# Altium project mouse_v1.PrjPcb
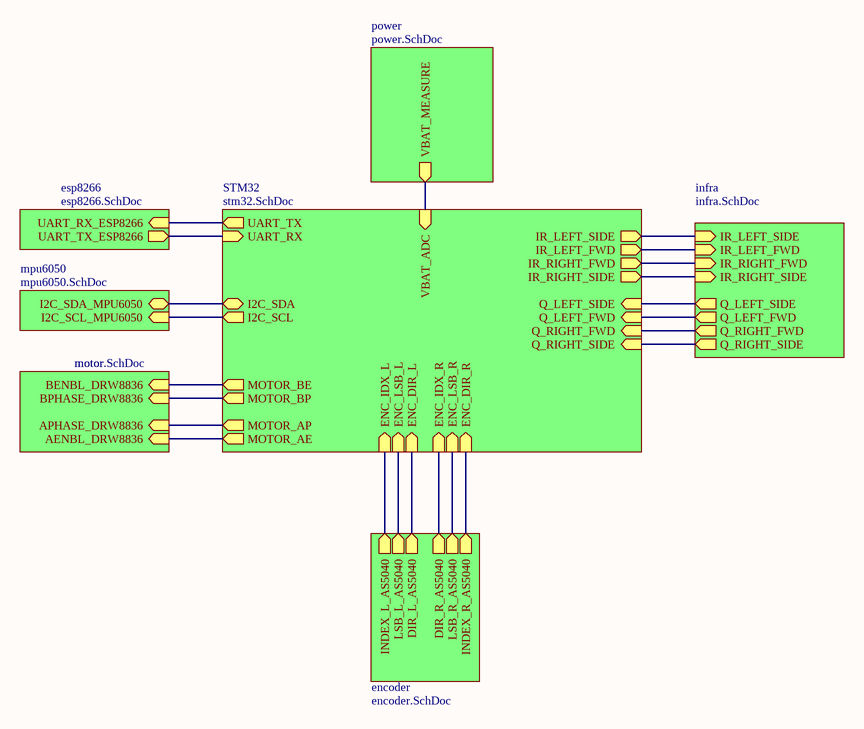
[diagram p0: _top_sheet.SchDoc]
8 sheets, 95 parts. Net scope: hierarchical (ports join the sheet entries above them; power ports are global).
Board file: grabovsky.PcbDoc
Sheets:
  _top_sheet.SchDoc
    STM32 = stm32.SchDoc
    infra = infra.SchDoc
    mpu6050 = mpu6050.SchDoc
    motor = motor.SchDoc
    power = power.SchDoc
    encoder = encoder.SchDoc
    esp8266 = esp8266.SchDoc

## Sheet _top_sheet.SchDoc
size A4

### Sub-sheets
encoder = encoder.SchDoc: INDEX_L_AS5040 (out), INDEX_R_AS5040 (out), LSB_L_AS5040 (out), DIR_L_AS5040 (out), DIR_R_AS5040 (out), LSB_R_AS5040 (out)
esp8266 = esp8266.SchDoc: UART_TX_ESP8266 (out), UART_RX_ESP8266 (in)
infra = infra.SchDoc: IR_LEFT_SIDE (in), IR_LEFT_FWD (in), IR_RIGHT_SIDE (in), IR_RIGHT_FWD (in), Q_LEFT_FWD (out), Q_LEFT_SIDE (out), Q_RIGHT_FWD (out), Q_RIGHT_SIDE (out)
motor = motor.SchDoc: AENBL_DRW8836 (in), APHASE_DRW8836 (in), BENBL_DRW8836 (in), BPHASE_DRW8836 (in)
mpu6050 = mpu6050.SchDoc: I2C_SCL_MPU6050 (in), I2C_SDA_MPU6050 (bidir)
power = power.SchDoc: VBAT_MEASURE (out)
STM32 = stm32.SchDoc: UART_TX (out), I2C_SDA (bidir), UART_RX (in), I2C_SCL (out), MOTOR_AE (out), MOTOR_BE (out), MOTOR_BP (out), MOTOR_AP (out), Q_RIGHT_FWD (in), Q_RIGHT_SIDE (in), Q_LEFT_FWD (in), Q_LEFT_SIDE (in), IR_LEFT_SIDE (out), IR_LEFT_FWD (out), IR_RIGHT_FWD (out), IR_RIGHT_SIDE (out), ENC_IDX_L (in), ENC_LSB_L (in), ENC_DIR_L (in), ENC_IDX_R (in), ENC_LSB_R (in), ENC_DIR_R (in), VBAT_ADC (in)

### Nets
VBAT: sheet STM32/VBAT_ADC, sheet power/VBAT_MEASURE
Net*1_3: sheet STM32/ENC_LSB_L, sheet encoder/LSB_L_AS5040
Net*1_4: sheet STM32/ENC_DIR_L, sheet encoder/DIR_L_AS5040
Net*1_6: sheet STM32/ENC_IDX_L, sheet encoder/INDEX_L_AS5040
Net*2_3: sheet STM32/ENC_LSB_R, sheet encoder/LSB_R_AS5040
Net*2_4: sheet STM32/ENC_IDX_R, sheet encoder/DIR_R_AS5040
Net*2_6: sheet STM32/ENC_DIR_R, sheet encoder/INDEX_R_AS5040
Netmosfet1_2: sheet STM32/IR_LEFT_FWD, sheet infra/IR_LEFT_FWD
Netmosfet1_5: sheet STM32/IR_LEFT_SIDE, sheet infra/IR_LEFT_SIDE
Netmosfet2_2: sheet STM32/IR_RIGHT_SIDE, sheet infra/IR_RIGHT_SIDE
Netmosfet2_5: sheet STM32/IR_RIGHT_FWD, sheet infra/IR_RIGHT_FWD
NetP3_2: sheet STM32/UART_TX, sheet esp8266/UART_RX_ESP8266
NetP3_3: sheet STM32/UART_RX, sheet esp8266/UART_TX_ESP8266
NetR9_3: sheet STM32/Q_LEFT_FWD, sheet infra/Q_LEFT_FWD
NetR10_3: sheet STM32/Q_LEFT_SIDE, sheet infra/Q_LEFT_SIDE
NetR11_3: sheet STM32/Q_RIGHT_SIDE, sheet infra/Q_RIGHT_SIDE
NetR12_3: sheet STM32/Q_RIGHT_FWD, sheet infra/Q_RIGHT_FWD
NetR16_1: sheet STM32/I2C_SDA, sheet mpu6050/I2C_SDA_MPU6050
NetR19_1: sheet STM32/I2C_SCL, sheet mpu6050/I2C_SCL_MPU6050
NetR28_1: sheet STM32/MOTOR_AP, sheet motor/APHASE_DRW8836
NetR29_1: sheet STM32/MOTOR_BP, sheet motor/BPHASE_DRW8836
NetR30_1: sheet STM32/MOTOR_BE, sheet motor/BENBL_DRW8836
NetR31_1: sheet STM32/MOTOR_AE, sheet motor/AENBL_DRW8836

## Sheet stm32.SchDoc
size A4
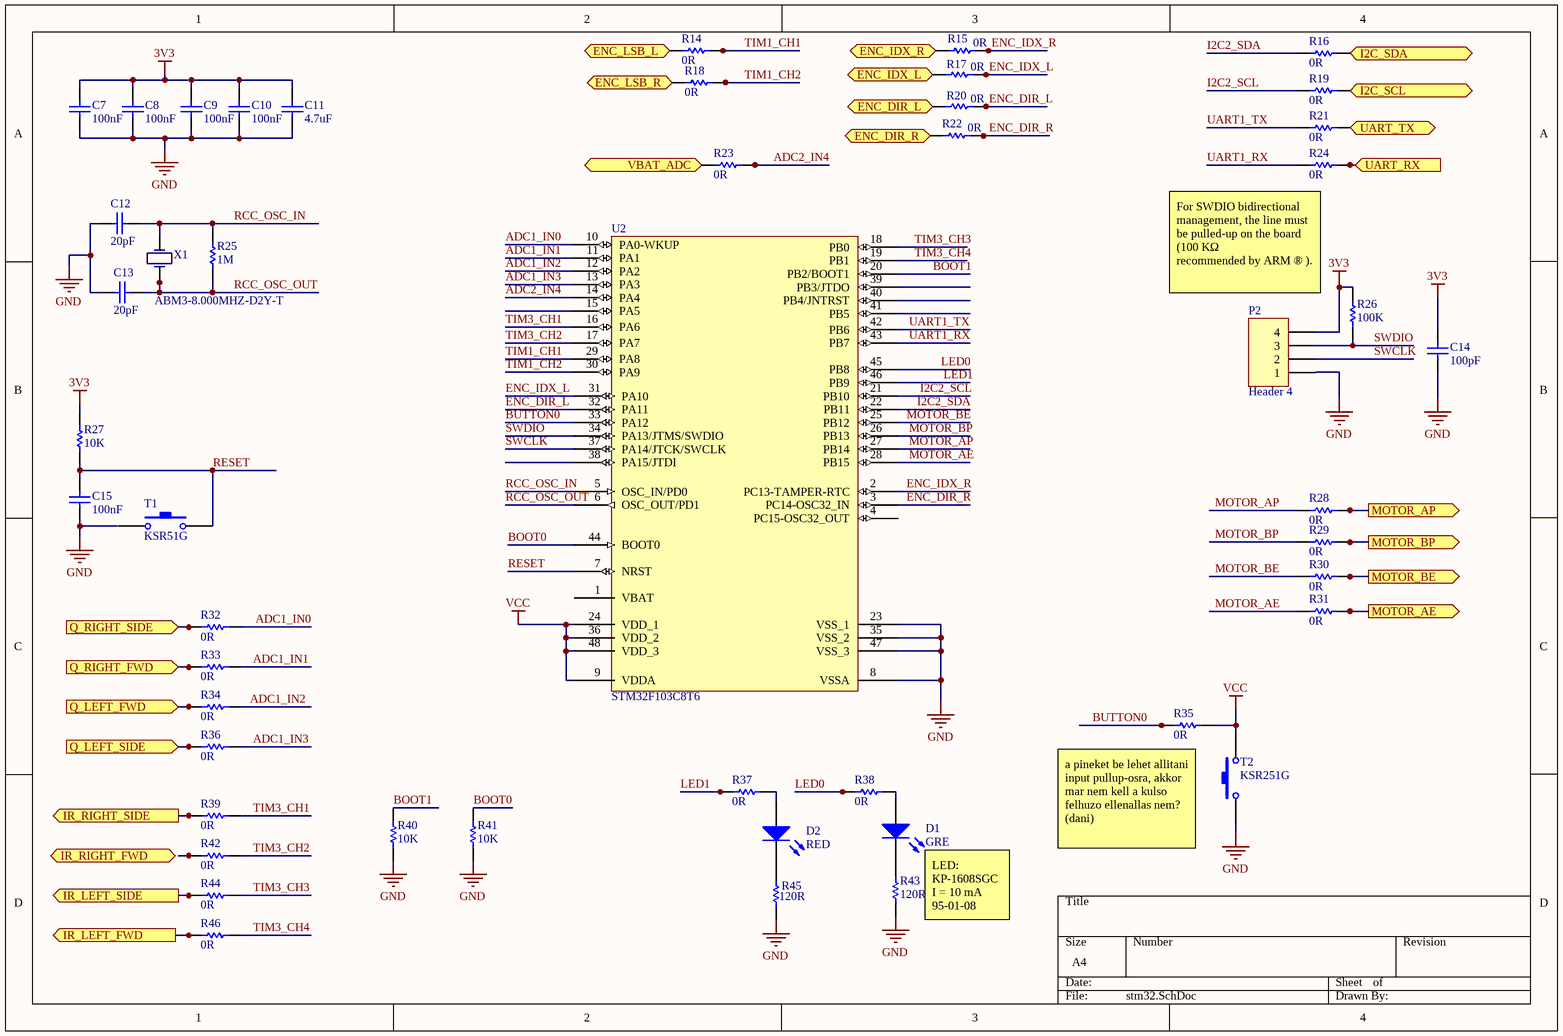
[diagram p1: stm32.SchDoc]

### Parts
C7  100nF  [0603]
C8  100nF  [0603]
C9  100nF  [0603]
C10  100nF  [0603]
C11  4.7uF  [0603]
C12  20pF  [0603]
C13  20pF  [0603]
C14  100pF  [0603]
C15  100nF  [0603]
D1  GRE  [1608[0603]]
D2  RED  [1608[0603]]
P2  Header 4  [HDR1X4]
R14  0R  [0402]
R15  0R  [0402]
R16  0R  [0402]
R17  0R  [0402]
R18  0R  [0402]
R19  0R  [0402]
R20  0R  [0402]
R21  0R  [0402]
R22  0R  [0402]
R23  0R  [0402]
R24  0R  [0402]
R25  1M  [0603]
R26  100K  [0603]
R27  10K  [0603]
R28  0R  [0402]
R29  0R  [0402]
R30  0R  [0402]
R31  0R  [0402]
R32  0R  [0402]
R33  0R  [0402]
R34  0R  [0402]
R35  0R  [0402]
R36  0R  [0402]
R37  0R  [0402]
R38  0R  [0402]
R39  0R  [0402]
R40  10K  [0603]
R41  10K  [0603]
R42  0R  [0402]
R43  120R  [0603]
R44  0R  [0402]
R45  120R  [0603]
R46  0R  [0402]
T1  KSR51G  [ksr251g]
T2  KSR251G  [ksr251g]
U2  STM32F103C8T6  [LQFP48_N]
X1  ABM3-8.000MHZ-D2Y-T  [Crystal]

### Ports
ENC_DIR_L (in), ENC_DIR_R (in), ENC_IDX_L (in), ENC_IDX_R (in), ENC_LSB_L (in), ENC_LSB_R (in), I2C_SCL (out), I2C_SDA (bidir), IR_LEFT_FWD (out), IR_LEFT_SIDE (out), IR_RIGHT_FWD (out), IR_RIGHT_SIDE (out), MOTOR_AE (out), MOTOR_AP (out), MOTOR_BE (out), MOTOR_BP (out), Q_LEFT_FWD (in), Q_LEFT_SIDE (in), Q_RIGHT_FWD (in), Q_RIGHT_SIDE (in), UART_RX (in), UART_TX (out), VBAT_ADC (in)

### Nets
3V3: C7.5 C8.5 C9.5 C10.5 C11.5 C14.5 P2.4 R26.4 R27.3
GND: C7.6 C8.6 C9.6 C10.6 C11.6 C12.5 C13.5 C14.6 C15.5 P2.1 R40.4 R41.4 R43.4 R45.4 T2.1 U2.8(VSSA) U2.23(VSS_1) U2.35(VSS_2) U2.47(VSS_3)
VBAT: R23.0 ; port VBAT_ADC
VCC: R35.1 T2.2 U2.9(VDDA) U2.24(VDD_1) U2.36(VDD_2) U2.48(VDD_3)
ADC1_IN0: R32.1 U2.10(PA0-WKUP)
ADC1_IN1: R33.1 U2.11(PA1)
ADC1_IN2: R34.1 U2.12(PA2)
ADC1_IN3: R36.1 U2.13(PA3)
ADC2_IN4: R23.1 U2.14(PA4)
BOOT0: R41.3 U2.44(BOOT0)
BOOT1: R40.3 U2.20(PB2/BOOT1)
BUTTON0: R35.0 U2.33(PA12)
ENC_DIR_L: R20.1 U2.32(PA11)
ENC_DIR_R: R22.1 U2.3(PC14-OSC32_IN)
ENC_IDX_L: R17.1 U2.31(PA10)
ENC_IDX_R: R15.1 U2.2(PC13-TAMPER-RTC)
I2C2_SCL: R19.0 U2.21(PB10)
I2C2_SDA: R16.0 U2.22(PB11)
LED0: R38.0 U2.45(PB8)
LED1: R37.0 U2.46(PB9)
MOTOR_AE: R31.0 U2.28(PB15)
MOTOR_AP: R28.0 U2.27(PB14)
MOTOR_BE: R30.0 U2.25(PB12)
MOTOR_BP: R29.0 U2.26(PB13)
RCC_OSC_IN: C12.6 R25.3 U2.5(OSC_IN/PD0) X1.2
RCC_OSC_OUT: C13.6 R25.4 U2.6(OSC_OUT/PD1) X1.1
RESET: C15.6 R27.4 T1.2 U2.7(NRST)
SWCLK: P2.2 U2.37(PA14/JTCK/SWCLK)
SWDIO: P2.3 R26.3 U2.34(PA13/JTMS/SWDIO)
TIM1_CH1: R14.1 U2.29(PA8)
TIM1_CH2: R18.1 U2.30(PA9)
TIM3_CH1: R39.1 U2.16(PA6)
TIM3_CH2: R42.1 U2.17(PA7)
TIM3_CH3: R44.1 U2.18(PB0)
TIM3_CH4: R46.1 U2.19(PB1)
UART1_RX: R24.0 U2.43(PB7)
UART1_TX: R21.0 U2.42(PB6)
Net*1_3: R14.0 ; port ENC_LSB_L
Net*1_4: R20.0 ; port ENC_DIR_L
Net*1_6: R17.0 ; port ENC_IDX_L
Net*2_3: R18.0 ; port ENC_LSB_R
Net*2_4: R15.0 ; port ENC_IDX_R
Net*2_6: R22.0 ; port ENC_DIR_R
NetD1_1: D1.1(A) R38.1
NetD2_1: D2.1(A) R37.1
NetD2_2: D2.2(K) R45.3
Netmosfet1_2: R46.0 ; port IR_LEFT_FWD
Netmosfet1_5: R44.0 ; port IR_LEFT_SIDE
Netmosfet2_2: R39.0 ; port IR_RIGHT_SIDE
NetP3_2: R21.1 ; port UART_TX
NetP3_3: R24.1 ; port UART_RX
NetR9_3: R34.0 ; port Q_LEFT_FWD
NetR10_3: R36.0 ; port Q_LEFT_SIDE
NetR11_3: R32.0 ; port Q_RIGHT_SIDE
NetR12_3: R33.0 ; port Q_RIGHT_FWD
NetR16_1: R16.1 ; port I2C_SDA
NetR19_1: R19.1 ; port I2C_SCL
NetR28_1: R28.1 ; port MOTOR_AP
NetR29_1: R29.1 ; port MOTOR_BP
NetR30_1: R30.1 ; port MOTOR_BE
NetR31_1: R31.1 ; port MOTOR_AE

Not connected (* = marked no-connect by the designer): D1 2(K); R42 0; R43 3; T1 1; U2 1(VBAT) 4(PC15-OSC32_OUT) 15(PA5) 38(PA15/JTDI) 39(PB3/JTDO) 40(PB4/JNTRST) 41(PB5)

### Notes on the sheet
- For SWDIO bidirectional management, the line must be pulled-up on the board (100 KΩ
  recommended by ARM ® ).
- a pineket be lehet allitani input pullup-osra, akkor mar nem kell a kulso felhuzo ellenallas nem? (dani)
- LED: KP-1608SGC
  I = 10 mA
  95-01-08

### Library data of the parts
C7-C15 = capacitor_0603
D1 D2 = LED0: Typical INFRARED GaAs LED
P2 = Header 4: Header, 4-Pin
R14-R24 R28-R39 R42 R44 R46 = resistor_0402
R25-R27 R40 R41 R43 R45 = resistor_0603
T1 T2 = ksr251g: tactile switch
U2 = STM32F103C8T6: STM32 ARM-based 32-bit MCU with 64 Kbytes Flash, 48-pin LQFP, Industrial Temperature
X1 = smd_crystal: Frequency: 8MHz

## Sheet infra.SchDoc
size A4
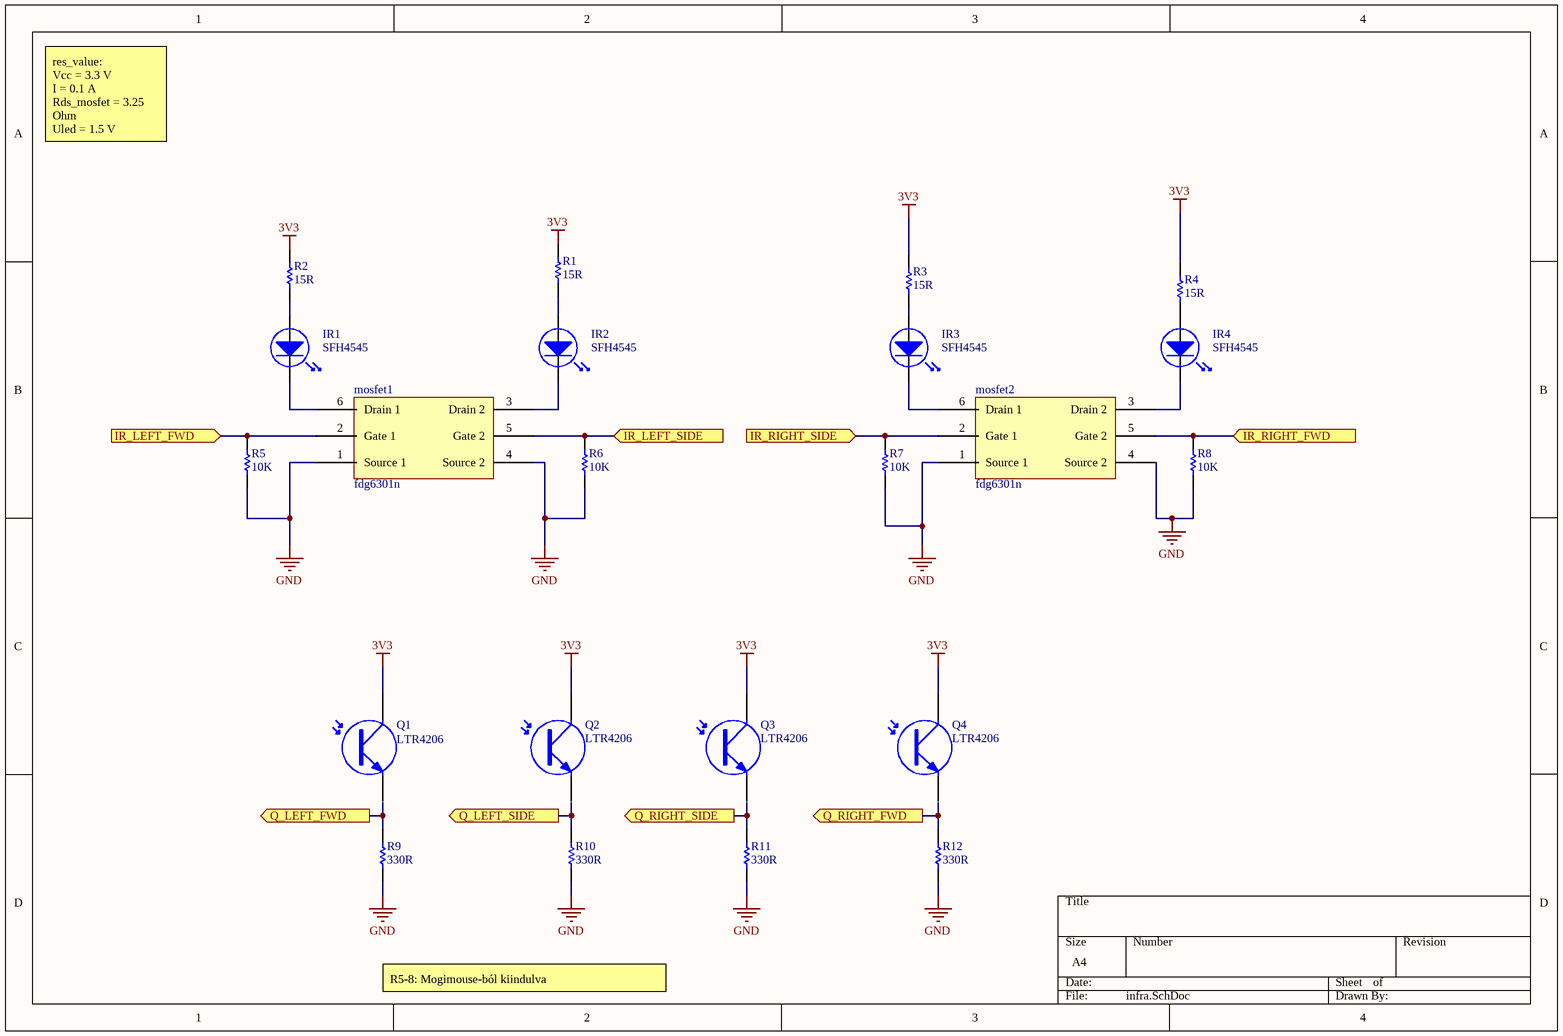
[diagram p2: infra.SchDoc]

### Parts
IR1  SFH4545  [IR Emitter]
IR2  SFH4545  [IR Emitter]
IR3  SFH4545  [IR Emitter]
IR4  SFH4545  [IR Emitter]
mosfet1  fdg6301n  [SC70-6]
mosfet2  fdg6301n  [SC70-6]
Q1  LTR4206  [PhotoTransistor]
Q2  LTR4206  [PhotoTransistor]
Q3  LTR4206  [PhotoTransistor]
Q4  LTR4206  [PhotoTransistor]
R1  15R  [0603]
R2  15R  [0603]
R3  15R  [0603]
R4  15R  [0603]
R5  10K  [0603]
R6  10K  [0603]
R7  10K  [0603]
R8  10K  [0603]
R9  330R  [0603]
R10  330R  [0603]
R11  330R  [0603]
R12  330R  [0603]

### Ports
IR_LEFT_FWD (in), IR_LEFT_SIDE (in), IR_RIGHT_FWD (in), IR_RIGHT_SIDE (in), Q_LEFT_FWD (out), Q_LEFT_SIDE (out), Q_RIGHT_FWD (out), Q_RIGHT_SIDE (out)

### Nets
3V3: Q1.1(C) Q2.1(C) Q3.1(C) Q4.1(C) R1.3 R2.3 R3.3 R4.3
GND: mosfet1.1(Source_1) mosfet1.4(Source_2) mosfet2.1(Source_1) mosfet2.4(Source_2) R5.4 R6.4 R7.4 R8.4 R9.4 R10.4 R11.4 R12.4
NetIR1_1: IR1.1(A) R2.4
NetIR1_2: IR1.2(K) mosfet1.6(Drain_1)
NetIR2_1: IR2.1(A) R1.4
NetIR2_2: IR2.2(K) mosfet1.3(Drain_2)
NetIR3_1: IR3.1(A) R3.4
NetIR3_2: IR3.2(K) mosfet2.6(Drain_1)
NetIR4_1: IR4.1(A) R4.4
NetIR4_2: IR4.2(K) mosfet2.3(Drain_2)
Netmosfet1_2: mosfet1.2(Gate_1) R5.3 ; port IR_LEFT_FWD
Netmosfet1_5: mosfet1.5(Gate_2) R6.3 ; port IR_LEFT_SIDE
Netmosfet2_2: mosfet2.2(Gate_1) R7.3 ; port IR_RIGHT_SIDE
Netmosfet2_5: mosfet2.5(Gate_2) R8.3 ; port IR_RIGHT_FWD
NetR9_3: R9.3 ; port Q_LEFT_FWD
NetR10_3: R10.3 ; port Q_LEFT_SIDE
NetR11_3: R11.3 ; port Q_RIGHT_SIDE
NetR12_3: R12.3 ; port Q_RIGHT_FWD

Not connected (* = marked no-connect by the designer): Q1 3(E); Q2 3(E); Q3 3(E); Q4 3(E)

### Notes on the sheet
- res_value:
  Vcc = 3.3 V
  I = 0.1 A
  Rds_mosfet = 3.25 Ohm
  Uled = 1.5 V
- R5-8: Mogimouse-ból kiindulva

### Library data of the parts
IR1-IR4 = SFH4545: IR Emitter Diode
R1-R12 = resistor_0603

## Sheet mpu6050.SchDoc
size A4
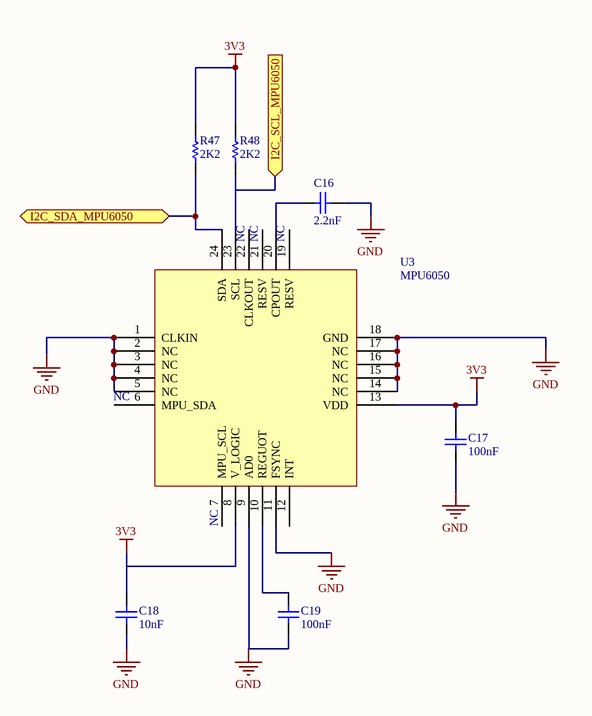
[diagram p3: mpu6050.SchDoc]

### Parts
C16  2.2nF  [0603]
C17  100nF  [0603]
C18  10nF  [0603]
C19  100nF  [0603]
R47  2K2  [0603]
R48  2K2  [0603]
U3  MPU6050  [MPU6050]

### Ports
I2C_SCL_MPU6050 (in), I2C_SDA_MPU6050 (bidir)

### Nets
3V3: C17.5 C18.5 R47.3 R48.3 U3.8(V_LOGIC) U3.13(VDD)
GND: C16.6 C17.6 C18.6 C19.6 U3.1(CLKIN) U3.2(NC) U3.3(NC) U3.4(NC) U3.9(AD0) U3.11(FSYNC) U3.14(NC) U3.15(NC) U3.16(NC) U3.17(NC) U3.18(GND)
NetC16_5: C16.5 U3.20(CPOUT)
NetC19_5: C19.5 U3.10(REGUOT)
NetR16_1: R47.4 U3.24(SDA) ; port I2C_SDA_MPU6050
NetR19_1: R48.4 U3.23(SCL) ; port I2C_SCL_MPU6050

Not connected (* = marked no-connect by the designer): U3 5(NC) 6(MPU_SDA) 7(MPU_SCL) 12(INT) 19(RESV) 21(RESV) 22(CLKOUT)

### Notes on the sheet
- (near U3) NC
- NC

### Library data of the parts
C16-C19 = capacitor_0603
R47 R48 = resistor_0603

## Sheet motor.SchDoc
size A4
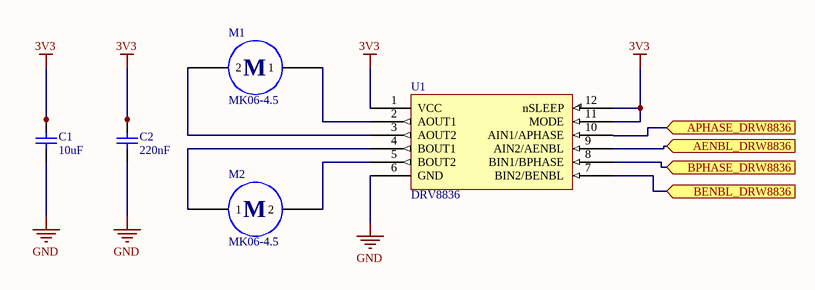
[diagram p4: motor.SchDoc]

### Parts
C1  10uF  [0603]
C2  220nF  [0603]
M1  MK06-4.5  [PCBComponent_1]
M2  MK06-4.5  [PCBComponent_1]
U1  DRV8836  [QFN0P300X200X80-12N]

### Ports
AENBL_DRW8836 (in), APHASE_DRW8836 (in), BENBL_DRW8836 (in), BPHASE_DRW8836 (in)

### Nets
3V3: C1.5 C2.5 U1.1(VCC) U1.11(MODE) U1.12(nSLEEP)
GND: C1.6 C2.6 U1.6(GND)
NetM1_0: M1.0(1) U1.2(AOUT1)
NetM1_1: M1.1(2) U1.3(AOUT2)
NetM2_0: M2.0(1) U1.4(BOUT1)
NetM2_1: M2.1(2) U1.5(BOUT2)
NetR28_1: U1.10(AIN1/APHASE) ; port APHASE_DRW8836
NetR29_1: U1.8(BIN1/BPHASE) ; port BPHASE_DRW8836
NetR30_1: U1.7(BIN2/BENBL) ; port BENBL_DRW8836
NetR31_1: U1.9(AIN2/AENBL) ; port AENBL_DRW8836

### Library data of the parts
C1 C2 = capacitor_0603
M1 M2 = motor

## Sheet power.SchDoc
size A4
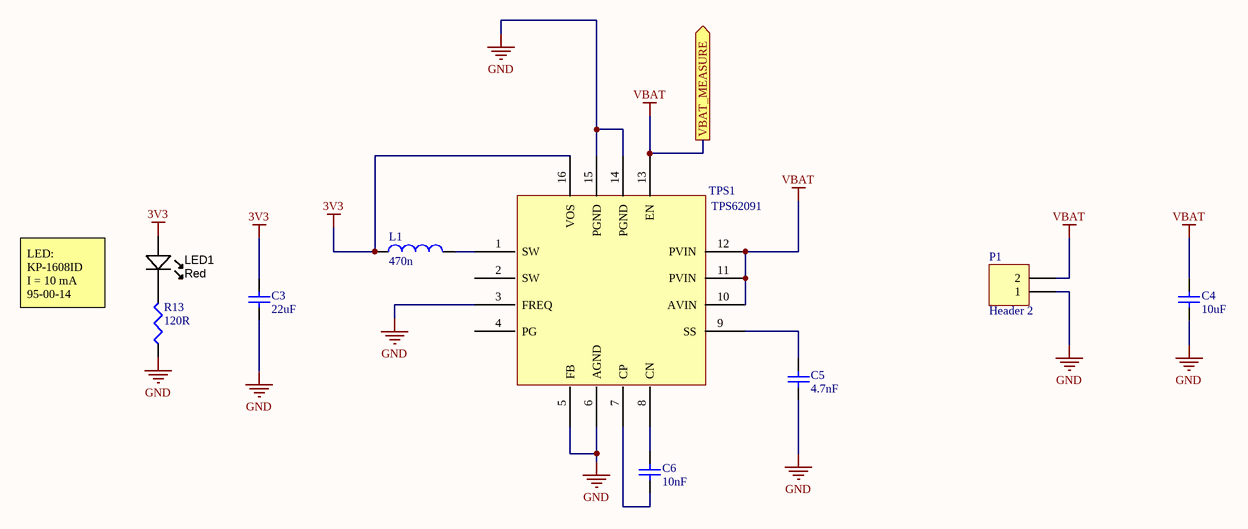
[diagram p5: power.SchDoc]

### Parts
C3  22uF  [0603]
C4  10uF  [0603]
C5  4.7nF  [0603]
C6  10nF  [0603]
L1  470n  [6-0805_N]
LED1  Red  [LED-0603-RED]
P1  Header 2  [HDR1X2]
R13  120R  [J1-0603]
TPS1  TPS62091  [QFN50P300X300X100_HS-17N]

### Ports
VBAT_MEASURE (out)

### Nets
3V3: C3.5 L1.1 LED1.A TPS1.16(VOS)
GND: C3.6 C4.6 C5.6 P1.1 R13.1 TPS1.3(FREQ) TPS1.5(FB) TPS1.6(AGND) TPS1.14(PGND) TPS1.15(PGND)
VBAT: C4.5 P1.2 TPS1.10(AVIN) TPS1.11(PVIN) TPS1.12(PVIN) TPS1.13(EN) ; port VBAT_MEASURE
NetC5_5: C5.5 TPS1.9(SS)
NetC6_5: C6.5 TPS1.8(CN)
NetC6_6: C6.6 TPS1.7(CP)
NetL1_2: L1.2 TPS1.1(SW)
NetLED1_K: LED1.K R13.2

Not connected (* = marked no-connect by the designer): TPS1 2(SW) 4(PG)

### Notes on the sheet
- LED: KP-1608ID
  I = 10 mA
  95-00-14

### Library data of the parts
C3-C6 = capacitor_0603
L1 = Inductor: Code_IEC: 1005
LED1 = LED_SMD_Red_0603_220mcd: LED 0603 SMD Hyper Red 630nm 220mcd 20mA; Manufacturer 1: Kingbright Company LLC; Manufacturer Part Number 1: APT1608SURCK; Material: AlGaInP on GaAs; Ratings: 220 mcd; 630 nm; Voltage - Forward (Vf) Typ: 1.95V; Voltage - Forward (Vf) @ 10mA: 1.9V; SCDType: source
P1 = Header 2: Header, 2-Pin
R13 = Res3: Resistor

## Sheet encoder.SchDoc
size A4
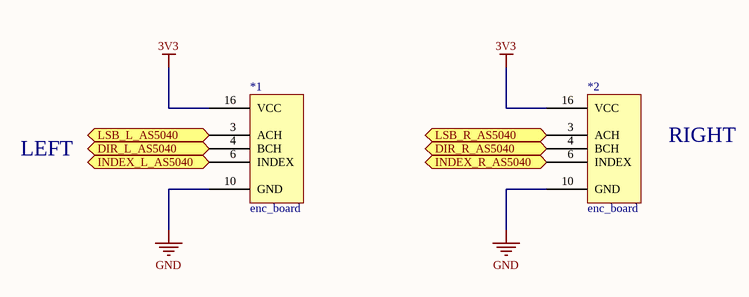
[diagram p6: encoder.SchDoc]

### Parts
*1  enc_board  [enc_board]
*2  enc_board  [enc_board]

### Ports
DIR_L_AS5040 (out), DIR_R_AS5040 (out), INDEX_L_AS5040 (out), INDEX_R_AS5040 (out), LSB_L_AS5040 (out), LSB_R_AS5040 (out)

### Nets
3V3: *1.16(VCC) *2.16(VCC)
GND: *1.10(GND) *2.10(GND)
Net*1_3: *1.3(ACH) ; port LSB_L_AS5040
Net*1_4: *1.4(BCH) ; port DIR_L_AS5040
Net*1_6: *1.6(INDEX) ; port INDEX_L_AS5040
Net*2_3: *2.3(ACH) ; port LSB_R_AS5040
Net*2_4: *2.4(BCH) ; port DIR_R_AS5040
Net*2_6: *2.6(INDEX) ; port INDEX_R_AS5040

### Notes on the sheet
- LEFT
- RIGHT

## Sheet esp8266.SchDoc
size A4
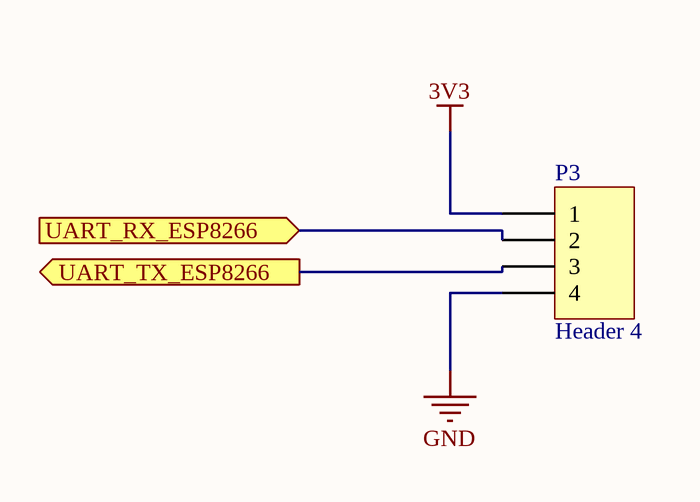
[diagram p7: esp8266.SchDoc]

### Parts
P3  Header 4  [HDR1X4]

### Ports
UART_RX_ESP8266 (in), UART_TX_ESP8266 (out)

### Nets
3V3: P3.1
GND: P3.4
NetP3_2: P3.2 ; port UART_RX_ESP8266
NetP3_3: P3.3 ; port UART_TX_ESP8266

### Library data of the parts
P3 = Header 4: Header, 4-Pin

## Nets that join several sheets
3V3: stm32 (9 pins), infra (8 pins), mpu6050 (6 pins), motor (5 pins), power (C3.5 L1.1 LED1.A TPS1.16), encoder (*1.16 *2.16), esp8266 (P3.1)
GND: stm32 (19 pins), infra (12 pins), mpu6050 (15 pins), motor (C1.6 C2.6 U1.6), power (10 pins), encoder (*1.10 *2.10), esp8266 (P3.4)
VBAT: stm32 (R23.0), power (6 pins)
Net*1_3: stm32 (R14.0), encoder (*1.3)
Net*1_4: stm32 (R20.0), encoder (*1.4)
Net*1_6: stm32 (R17.0), encoder (*1.6)
Net*2_3: stm32 (R18.0), encoder (*2.3)
Net*2_4: stm32 (R15.0), encoder (*2.4)
Net*2_6: stm32 (R22.0), encoder (*2.6)
Netmosfet1_2: stm32 (R46.0), infra (mosfet1.2 R5.3)
Netmosfet1_5: stm32 (R44.0), infra (mosfet1.5 R6.3)
Netmosfet2_2: stm32 (R39.0), infra (mosfet2.2 R7.3)
NetP3_2: stm32 (R21.1), esp8266 (P3.2)
NetP3_3: stm32 (R24.1), esp8266 (P3.3)
NetR9_3: stm32 (R34.0), infra (R9.3)
NetR10_3: stm32 (R36.0), infra (R10.3)
NetR11_3: stm32 (R32.0), infra (R11.3)
NetR12_3: stm32 (R33.0), infra (R12.3)
NetR16_1: stm32 (R16.1), mpu6050 (R47.4 U3.24)
NetR19_1: stm32 (R19.1), mpu6050 (R48.4 U3.23)
NetR28_1: stm32 (R28.1), motor (U1.10)
NetR29_1: stm32 (R29.1), motor (U1.8)
NetR30_1: stm32 (R30.1), motor (U1.7)
NetR31_1: stm32 (R31.1), motor (U1.9)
